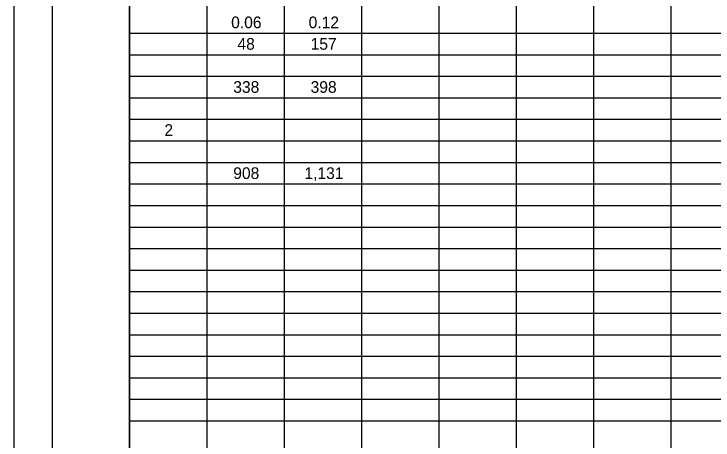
# Model space of a CAD drawing. Extents: x -50.3 to 36.4, y 0 to 22.5.
# Drawn here: x 0 to 9.08, y 10.89 to 16.43 of the extents above; entities that cross this region are included whole.
import ezdxf

# ---------------------------------------------------------------- set-up
doc = ezdxf.new("R2010")
doc.units = 0
for name, color, linetype in [('SH_Border', 7, 'Continuous'), ('SH_Cut_Line', 7, 'Continuous'), ('SH_Data', 7, 'Continuous'), ('SH_Text', 7, 'Continuous')]:
    doc.layers.add(name, color=color, linetype=linetype)

msp = doc.modelspace()

# ---------------------------------------------------------------- linework, layer by layer
at = {"layer": 'SH_Border'}
for points in [[(0.5, 21.5), (1.5, 21.5), (1.5, 0.5), (0.5, 0.5)], [(1.5, 21.5), (33.5, 21.5), (33.5, 0.5), (1.5, 0.5)]]:
    msp.add_lwpolyline(points, close=True, dxfattribs=at)
at = {"layer": 'SH_Cut_Line'}
msp.add_lwpolyline([(0, 0), (34, 0), (34, 22), (0, 22)], close=True, dxfattribs=at)
at = {"layer": 'SH_Data'}
for p, q in [((1.5, 21.5), (1.5, 0.5016)), ((2.5046, 20.94), (2.5046, 0.5016)), ((3.5093, 20.94), (3.5093, 0.5016)), ((4.5139, 20.94), (4.5139, 0.5016)), ((5.5185, 20.94), (5.5185, 0.5016)), ((6.5231, 20.94), (6.5231, 0.5016)), ((7.5278, 20.94), (7.5278, 0.5016)), ((8.5324, 20.94), (8.5324, 0.5016)), ((1.5, 16.1804), (32.0011, 16.1804)), ((1.5, 15.9004), (32.0011, 15.9004)), ((1.5, 15.6205), (32.0011, 15.6205)), ((1.5, 15.3405), (32.0011, 15.3405)), ((1.5, 15.0605), (32.0011, 15.0605)), ((1.5, 14.7805), (32.0011, 14.7805)), ((1.5, 14.5005), (32.0011, 14.5005)), ((1.5, 14.2206), (32.0011, 14.2206)), ((1.5, 13.9406), (32.0011, 13.9406)), ((1.5, 13.6606), (32.0011, 13.6606)), ((1.5, 13.3806), (32.0011, 13.3806)), ((1.5, 13.1007), (32.0011, 13.1007)), ((1.5, 12.8207), (32.0011, 12.8207)), ((1.5, 12.5407), (32.0011, 12.5407)), ((1.5, 12.2607), (32.0011, 12.2607)), ((1.5, 11.9807), (32.0011, 11.9807)), ((1.5, 11.7008), (32.0011, 11.7008)), ((1.5, 11.4208), (32.0011, 11.4208)), ((1.5, 11.1408), (32.0011, 11.1408))]:
    msp.add_line(p, q, dxfattribs=at)

# ---------------------------------------------------------------- texts
at = {"layer": 'SH_Text'}
for s, height, p in [('0.06', 0.15152, (2.8208, 16.2446)), ('0.12', 0.15152, (3.8271, 16.2446)), ('48', 0.15152, (2.9025, 15.9647)), ('157', 0.15152, (3.8532, 15.9647)), ('338', 0.15152, (2.8481, 15.4047)), ('398', 0.15152, (3.8527, 15.4047)), ('2', 0.1515, (1.9538, 14.8448)), ('908', 0.15152, (2.8481, 14.2848)), ('1,131', 0.15152, (3.7729, 14.2848))]:
    msp.add_text(s, height=height, dxfattribs=at).set_placement(p)

doc.saveas('drawing.dxf')
